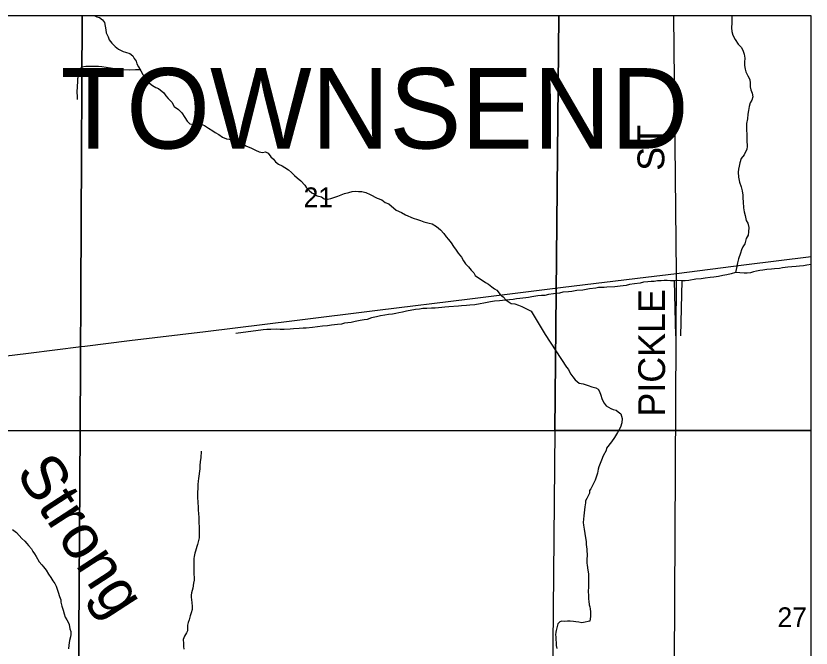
# Model space of a CAD drawing. Extents: x -8.5 to 18.7, y -20.3 to 7.
# Drawn here: x 15.375 to 18.741, y 4.26 to 6.938 of the extents above; entities that cross this region are included whole.
import ezdxf

# ---------------------------------------------------------------- set-up
doc = ezdxf.new("R2010")
doc.units = 0
for name, color, linetype in [('Default', 7, 'Continuous'), ('GM_X_Corporation', 7, 'Continuous'), ('GM_X_County_Road', 7, 'Continuous'), ('GM_X_County_Road_Text', 7, 'Continuous'), ('GM_X_Minor_River', 7, 'Continuous'), ('GM_X_Minor_River_Text', 7, 'Continuous'), ('GM_X_Section', 7, 'Continuous'), ('GM_X_Section_Text', 7, 'Continuous'), ('GM_X_State_Route', 7, 'Continuous'), ('GM_X_Township_Text', 7, 'Continuous'), ('SH_Cut_Line', 7, 'Continuous')]:
    doc.layers.add(name, color=color, linetype=linetype)

msp = doc.modelspace()

# ---------------------------------------------------------------- linework, layer by layer
at = {"layer": 'Default'}
for points in [[(15.6554, 6.938), (13.674, 6.938), (13.6421, 5.1822), (15.6471, 5.1817)], [(17.6737, 6.938), (15.6554, 6.938), (15.6471, 5.1817), (17.6568, 5.1811)], [(18.7413, 5.1812), (18.7413, 6.938), (17.6737, 6.938), (17.6568, 5.1811)], [(18.7413, 3.1985), (18.7413, 5.1812), (17.6568, 5.1811), (17.6382, 3.208)]]:
    msp.add_lwpolyline(points, close=True, dxfattribs=at)
at = {"layer": 'GM_X_Corporation'}
msp.add_lwpolyline([(18.7413, 1.1834), (18.7413, 6.938), (11.7049, 6.938), (11.6732, 5.0475), (11.6689, 4.6186), (11.6686, 4.5917), (11.6653, 4.2586), (11.64, 3.2551), (11.6132, 2.2462), (11.5871, 1.2389), (13.587, 1.2234), (15.5804, 1.208), (17.3261, 1.1944), (18.0915, 1.1885)], close=True, dxfattribs=at)
at = {"layer": 'GM_X_County_Road'}
msp.add_lwpolyline([(18.1302, 1.6994), (18.1318, 1.8143), (18.1389, 2.2013), (18.1465, 2.7014), (18.1506, 2.9396), (18.1537, 3.095), (18.1543, 3.1212), (18.1565, 3.3035), (18.1628, 4.1924), (18.1717, 5.8471), (18.1598, 6.938)], dxfattribs=at)
at = {"layer": 'GM_X_Minor_River'}
for p, q in [((18.162, 5.8153), (18.1668, 5.5828)), ((18.1942, 5.8159), (18.1888, 5.5826))]:
    msp.add_line(p, q, dxfattribs=at)
for points in [[(15.7101, 6.938), (15.7174, 6.9344), (15.7288, 6.9306), (15.7426, 6.9208), (15.7502, 6.9094), (15.7557, 6.8783), (15.758, 6.8662), (15.7657, 6.8487), (15.7703, 6.8366), (15.781, 6.8229), (15.7955, 6.8078), (15.8092, 6.7972), (15.829, 6.7874), (15.8397, 6.7837), (15.8571, 6.7784), (15.8701, 6.7694), (15.8762, 6.7572), (15.8839, 6.7466), (15.8877, 6.7345), (15.8946, 6.7216), (15.9046, 6.7049), (15.9123, 6.689), (15.9191, 6.6776), (15.9276, 6.6655), (15.9405, 6.6527), (15.9535, 6.6436), (15.9672, 6.6353), (15.9786, 6.6308), (16.0022, 6.6119), (16.0099, 6.5998), (16.0206, 6.5876), (16.0358, 6.5718), (16.0458, 6.5536), (16.0633, 6.5415), (16.0778, 6.5279), (16.0908, 6.5082), (16.1, 6.4923), (16.1115, 6.4801), (16.1274, 6.4772), (16.1418, 6.4772), (16.1593, 6.4796), (16.1737, 6.4735), (16.1913, 6.463), (16.2088, 6.4509), (16.2194, 6.4433), (16.2339, 6.435), (16.2499, 6.4237), (16.2674, 6.4169), (16.278, 6.4162), (16.2894, 6.414), (16.3084, 6.4103), (16.3267, 6.3982), (16.3381, 6.3944), (16.3488, 6.3876), (16.3731, 6.3771), (16.3899, 6.3688), (16.4051, 6.362), (16.4195, 6.3598), (16.4317, 6.3614), (16.4431, 6.3561), (16.4538, 6.3402), (16.4652, 6.3304), (16.4736, 6.3198), (16.4866, 6.3099), (16.5026, 6.3032), (16.514, 6.2964), (16.5292, 6.2858), (16.5414, 6.2744), (16.5544, 6.2616), (16.5658, 6.2518), (16.5811, 6.2389), (16.5979, 6.2215), (16.6048, 6.2094), (16.617, 6.198), (16.6276, 6.189), (16.6383, 6.1844), (16.6512, 6.1761), (16.6687, 6.1709), (16.6809, 6.1633), (16.6961, 6.1619), (16.7082, 6.1642)], [(18.4056, 6.938), (18.4056, 6.9357), (18.4057, 6.9221), (18.4057, 6.9092), (18.4051, 6.8879), (18.4059, 6.8719), (18.4106, 6.8568), (18.4198, 6.8386), (18.4328, 6.8181), (18.445, 6.8053), (18.4526, 6.7931), (18.458, 6.7757), (18.4604, 6.759), (18.4597, 6.7415), (18.459, 6.7278), (18.4629, 6.7126), (18.4653, 6.7005), (18.4737, 6.6838), (18.4814, 6.6679), (18.4837, 6.6527), (18.4838, 6.6368), (18.4869, 6.6246), (18.4923, 6.6102), (18.4946, 6.595), (18.4901, 6.5813), (18.4841, 6.5692), (18.4796, 6.5547), (18.4759, 6.5365), (18.4737, 6.522), (18.4716, 6.5015), (18.4679, 6.4818)], [(15.902, 6.7112), (15.9024, 6.7097), (15.8812, 6.7088), (15.8583, 6.7079), (15.8181, 6.7091), (15.8023, 6.7126), (15.7758, 6.7171), (15.7395, 6.722), (15.7251, 6.7232), (15.7008, 6.7231), (15.6864, 6.7235), (15.672, 6.7232), (15.6537, 6.7214), (15.6449, 6.7057), (15.6405, 6.6861), (15.6363, 6.6718), (15.6359, 6.6573), (15.6347, 6.6414), (15.6339, 6.6126), (15.6343, 6.5989), (15.6354, 6.5844)], [(18.4679, 6.4818), (18.4672, 6.4673), (18.4673, 6.4536), (18.4689, 6.4369), (18.4697, 6.424), (18.4697, 6.4119), (18.4714, 6.3853), (18.4699, 6.3731), (18.4579, 6.3488), (18.4458, 6.3335), (18.4399, 6.316), (18.4369, 6.3008), (18.4347, 6.2887), (18.4332, 6.2758), (18.4341, 6.2545), (18.4388, 6.234), (18.4449, 6.2143), (18.4496, 6.1968), (18.4519, 6.1786), (18.4528, 6.1657), (18.4536, 6.1498), (18.4552, 6.1247), (18.4584, 6.108), (18.4622, 6.0921), (18.4669, 6.0716), (18.4738, 6.0594), (18.4784, 6.0412), (18.4763, 6.0237), (18.4748, 6.0093), (18.4658, 5.9956), (18.4606, 5.972), (18.4523, 5.9591), (18.447, 5.9469), (18.4418, 5.9332), (18.4343, 5.9081), (18.4299, 5.8914), (18.4269, 5.8769), (18.4209, 5.8511)], [(16.7082, 6.1642), (16.7211, 6.1688), (16.7385, 6.1742), (16.7658, 6.1849), (16.784, 6.1896), (16.7984, 6.1942), (16.8121, 6.195), (16.825, 6.1943), (16.8394, 6.1936), (16.8561, 6.1891), (16.8752, 6.1816), (16.9048, 6.1657), (16.9239, 6.1582), (16.9391, 6.1476), (16.9535, 6.1424), (16.9856, 6.1144), (17.0076, 6.1046), (17.0244, 6.0948), (17.0563, 6.0812), (17.0746, 6.0752), (17.0875, 6.0715), (17.1027, 6.0662), (17.124, 6.0602), (17.1369, 6.0565), (17.156, 6.0459), (17.172, 6.0323), (17.1865, 6.0157), (17.1972, 6.0013), (17.2063, 5.9907), (17.2178, 5.9771), (17.2278, 5.9604), (17.2385, 5.946), (17.2476, 5.9323), (17.2614, 5.9165), (17.2698, 5.9005), (17.279, 5.8877), (17.2912, 5.8748), (17.3027, 5.8604), (17.3133, 5.8491), (17.3195, 5.8384), (17.3332, 5.8279), (17.3454, 5.8211), (17.3629, 5.809), (17.3758, 5.8014), (17.3896, 5.7901), (17.401, 5.7818), (17.4116, 5.7758), (17.4254, 5.7583), (17.4384, 5.7478), (17.4506, 5.7334), (17.4719, 5.7198), (17.4879, 5.7176), (17.5023, 5.7131), (17.5168, 5.7063), (17.5305, 5.6995), (17.5419, 5.6935), (17.5563, 5.6867), (17.6153, 5.5889)], [(18.7413, 5.8852), (18.7229, 5.8819), (18.7085, 5.8796), (18.6918, 5.878), (18.6782, 5.8764), (18.6592, 5.8748), (18.6425, 5.8732), (18.6198, 5.8701), (18.6069, 5.8685), (18.5864, 5.8662), (18.5742, 5.8654), (18.5537, 5.863), (18.537, 5.8607), (18.5249, 5.8591), (18.5105, 5.8568), (18.4976, 5.8537), (18.4855, 5.8498), (18.4711, 5.8475), (18.4574, 5.8474), (18.4209, 5.8511)], [(18.4209, 5.8511), (18.4035, 5.8457), (18.3846, 5.8411), (18.3671, 5.8387), (18.3497, 5.8341), (18.3299, 5.831), (18.3148, 5.8294), (18.2928, 5.8271), (18.2761, 5.8239), (18.2533, 5.8223), (18.2237, 5.8177), (18.2078, 5.8161), (18.1941, 5.816), (18.1767, 5.8167), (18.1607, 5.8159), (18.1456, 5.8158), (18.1319, 5.8165), (18.1197, 5.8165), (18.1068, 5.8157), (18.0909, 5.8156), (18.0765, 5.8133), (18.0643, 5.8125), (18.0507, 5.8117), (18.0325, 5.8093), (18.0181, 5.8062), (17.9938, 5.8031), (17.9725, 5.8), (17.9581, 5.7961), (17.9331, 5.793), (17.9103, 5.7899), (17.8769, 5.789), (17.8648, 5.7874), (17.842, 5.7873), (17.8299, 5.785), (17.8033, 5.7818), (17.7753, 5.7764), (17.7502, 5.774), (17.7282, 5.7709), (17.7146, 5.7693), (17.6911, 5.767), (17.6759, 5.7631), (17.6516, 5.76), (17.6304, 5.7576), (17.6137, 5.7538), (17.6008, 5.7529), (17.5849, 5.7514), (17.5598, 5.7482), (17.5454, 5.7451), (17.5333, 5.7436), (17.5211, 5.7428), (17.509, 5.7412), (17.4946, 5.7389), (17.4809, 5.7365), (17.4642, 5.7349), (17.4475, 5.7341), (17.4217, 5.731), (17.4013, 5.7294), (17.3846, 5.727), (17.3565, 5.7216), (17.3406, 5.7185), (17.3186, 5.7139), (17.2966, 5.713), (17.2822, 5.7114), (17.2617, 5.7098), (17.2495, 5.7083), (17.2086, 5.7051), (17.1911, 5.7035), (17.179, 5.7027), (17.1638, 5.7011), (17.1501, 5.7003), (17.1349, 5.7002), (17.1144, 5.6986), (17.0978, 5.6978), (17.0841, 5.6962), (17.0674, 5.6939), (17.0287, 5.6869), (17.012, 5.683), (16.9969, 5.6799), (16.9832, 5.6769), (16.9688, 5.6745), (16.9529, 5.6729), (16.9369, 5.6706), (16.918, 5.6667), (16.9021, 5.6636), (16.8801, 5.659), (16.8626, 5.6521), (16.849, 5.6505), (16.8331, 5.6474), (16.8111, 5.6428), (16.7944, 5.6397), (16.7663, 5.6365), (16.7542, 5.6327), (16.7367, 5.6311), (16.7109, 5.6272), (16.695, 5.6248), (16.6738, 5.6232), (16.6525, 5.6209), (16.6305, 5.6185), (16.604, 5.6154), (16.5918, 5.6146), (16.5751, 5.6137)], [(16.5751, 5.6137), (16.5501, 5.6121), (16.5357, 5.6105), (16.5106, 5.6097), (16.4939, 5.6096), (16.4764, 5.6103), (16.4544, 5.6095), (16.4377, 5.6094), (16.4218, 5.6086), (16.3057, 5.5918)], [(17.6153, 5.5889), (17.7063, 5.4505), (17.7139, 5.4399), (17.7193, 5.4301), (17.7247, 5.4195), (17.7323, 5.4096), (17.743, 5.3968), (17.759, 5.3824), (17.7765, 5.3787), (17.797, 5.3727), (17.8138, 5.366), (17.8297, 5.363), (17.8404, 5.357), (17.8458, 5.3471), (17.8519, 5.3319), (17.8558, 5.3175), (17.8596, 5.3069), (17.865, 5.2971), (17.8734, 5.2857), (17.8939, 5.2744), (17.9038, 5.2699), (17.916, 5.2677), (17.9251, 5.2609), (17.9358, 5.2518), (17.9412, 5.2321), (17.9406, 5.2138), (17.9346, 5.1956), (17.9225, 5.1735), (17.909, 5.1522), (17.8962, 5.1331), (17.8758, 5.1064), (17.8743, 5.0965), (17.8615, 5.0744), (17.854, 5.0562), (17.8428, 5.028), (17.8398, 5.0173), (17.8391, 5.009), (17.8369, 5.0006), (17.8309, 4.9839), (17.8279, 4.9717), (17.8166, 4.9489), (17.8091, 4.9351), (17.8038, 4.9268), (17.8031, 4.9154), (17.7918, 4.8933), (17.7866, 4.8834), (17.7866, 4.875), (17.7837, 4.8575), (17.7793, 4.8195), (17.7772, 4.7922), (17.778, 4.7808), (17.7811, 4.7641), (17.7835, 4.7451), (17.789, 4.7094), (17.7898, 4.698), (17.7922, 4.6783), (17.7931, 4.6486), (17.7924, 4.6388), (17.7925, 4.619), (17.7933, 4.6107), (17.7964, 4.5902), (17.7995, 4.575), (17.7996, 4.5636), (17.7989, 4.5507), (17.7997, 4.5362), (17.799, 4.5165), (17.7983, 4.5028), (17.7985, 4.4793), (17.7993, 4.4671), (17.8001, 4.4587), (17.8024, 4.4436), (17.8048, 4.4345), (17.8056, 4.4261), (17.8071, 4.4139), (17.8072, 4.3942), (17.8065, 4.3836), (17.8043, 4.3744), (17.7785, 4.3682), (17.7702, 4.3667), (17.758, 4.3689), (17.7451, 4.3704), (17.7352, 4.3718), (17.7216, 4.374), (17.7109, 4.374), (17.698, 4.3724), (17.6859, 4.3739), (17.6775, 4.3716), (17.6692, 4.3624), (17.6625, 4.335), (17.6603, 4.3266), (17.6596, 4.316), (17.6604, 4.3076), (17.6628, 4.2704), (17.6644, 4.2575)], [(16.16, 5.0945), (16.1579, 5.0656), (16.1557, 5.0496), (16.1543, 5.0322), (16.1536, 5.0185), (16.1485, 4.9782), (16.147, 4.9668), (16.1448, 4.9531), (16.1448, 4.9432), (16.1435, 4.9136), (16.1436, 4.8984), (16.1452, 4.8779), (16.1468, 4.8551), (16.1476, 4.843), (16.1484, 4.8316), (16.1493, 4.8111), (16.1494, 4.8012), (16.1502, 4.7898), (16.151, 4.7731), (16.1512, 4.7442), (16.1505, 4.7275), (16.1468, 4.71), (16.1438, 4.6993), (16.1408, 4.6902), (16.1363, 4.6704), (16.1334, 4.6613), (16.1304, 4.6484), (16.1289, 4.64), (16.1282, 4.6301), (16.1283, 4.602), (16.1292, 4.5838), (16.1294, 4.5481), (16.1272, 4.5344), (16.1242, 4.5131), (16.1182, 4.4941), (16.1175, 4.4834), (16.1176, 4.4751), (16.1207, 4.4523), (16.1216, 4.4364), (16.1209, 4.4234), (16.1179, 4.409), (16.1134, 4.3961), (16.109, 4.3793), (16.1052, 4.3679), (16.1022, 4.3565), (16.1015, 4.3436), (16.1023, 4.3329), (16.0978, 4.3238), (16.0888, 4.3108), (16.0828, 4.2956), (16.0844, 4.2797), (16.0845, 4.2668), (16.0868, 4.2554)], [(15.3615, 4.7617), (15.3775, 4.7489), (15.3897, 4.7368), (15.4004, 4.7247), (15.4126, 4.7126), (15.421, 4.7028), (15.4286, 4.6937), (15.4409, 4.6801), (15.4477, 4.6695), (15.4539, 4.6588), (15.4608, 4.6482), (15.4745, 4.6255), (15.4852, 4.6126), (15.4921, 4.6043), (15.5036, 4.5892), (15.5135, 4.5725), (15.5227, 4.5589), (15.5311, 4.5453), (15.5395, 4.5331), (15.5464, 4.5225), (15.5503, 4.5096), (15.5541, 4.4967), (15.5603, 4.4785), (15.5649, 4.4641), (15.5657, 4.4542), (15.5696, 4.4375), (15.575, 4.4209), (15.5797, 4.4049), (15.5843, 4.3905), (15.5904, 4.3799), (15.5965, 4.3701), (15.6004, 4.3594), (15.6043, 4.342), (15.6074, 4.3298), (15.6074, 4.3169)], [(15.6074, 4.3169), (15.606, 4.307), (15.6022, 4.2918), (15.6001, 4.2721), (15.5986, 4.2561)]]:
    msp.add_lwpolyline(points, dxfattribs=at)
at = {"layer": 'GM_X_Section'}
for points in [[(15.6471, 5.1817), (15.6347, 3.2252), (13.6222, 3.2394), (13.6421, 5.1822)], [(17.6568, 5.1811), (17.6382, 3.208), (15.6347, 3.2252), (15.6471, 5.1817)]]:
    msp.add_lwpolyline(points, close=True, dxfattribs=at)
at = {"layer": 'GM_X_State_Route'}
for points in [[(15.667, 5.5395), (15.8567, 5.5635), (16.1776, 5.6014), (16.5549, 5.6474), (16.9064, 5.692), (17.2971, 5.74), (17.6912, 5.7893), (18.0412, 5.8317), (18.1717, 5.8471), (18.4567, 5.8827), (18.7413, 5.9187)], [(10.687, 4.9287), (10.7287, 4.9346), (10.9024, 4.9549), (11.2577, 4.9986), (11.5812, 5.0354), (11.6736, 5.0464), (11.6869, 5.048), (12.1416, 5.1052), (12.4869, 5.1498), (12.8209, 5.1899), (13.2111, 5.2354), (13.5617, 5.2783), (13.645, 5.2895), (13.909, 5.3237), (14.2377, 5.3664), (14.6621, 5.4171), (14.8198, 5.4359), (15.1611, 5.4766), (15.4293, 5.5094), (15.6511, 5.5375), (15.667, 5.5395)]]:
    msp.add_lwpolyline(points, dxfattribs=at)
at = {"layer": 'SH_Cut_Line'}
msp.add_lwpolyline([(18.7413, -10.9039), (18.7413, 6.938), (-8.4587, 6.938)], dxfattribs=at)

# ---------------------------------------------------------------- texts
at = {"layer": 'GM_X_County_Road_Text'}
for s, p in [('ST', (18.1201, 6.2818)), ('PICKLE', (18.1234, 5.2402))]:
    msp.add_text(s, height=0.11364, rotation=90, dxfattribs=at).set_placement(p)
at = {"layer": 'GM_X_Minor_River_Text'}
msp.add_text('Strong', height=0.18951, rotation=303.0077, dxfattribs=at).set_placement((15.3717, 5.0027))
at = {"layer": 'GM_X_Section_Text'}
for s, p in [('21', (16.5931, 6.1276)), ('27', (18.599, 4.3486))]:
    msp.add_text(s, height=0.08371, rotation=0, dxfattribs=at).set_placement(p)
at = {"layer": 'GM_X_Township_Text'}
msp.add_text('TOWNSEND', height=0.34091, rotation=0, dxfattribs=at).set_placement((15.5639, 6.376))

doc.saveas('drawing.dxf')
